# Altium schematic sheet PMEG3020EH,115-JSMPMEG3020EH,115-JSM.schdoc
size 127 x 101 mm
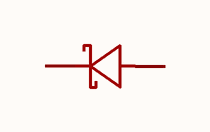
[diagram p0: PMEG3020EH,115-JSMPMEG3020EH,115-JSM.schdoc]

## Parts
D?  pmeg3020eh,115-jsm  [SOD-123FL_L2.7-W1.8-LS3.7-RD]  (value not drawn)

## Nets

Not connected (* = marked no-connect by the designer): D? 1(K) 2(A)

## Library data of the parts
D? = pmeg3020eh,115-jsm: 二极管配置:1个独立式;正向压降(Vf):550mV@3A;直流反向耐压(Vr):20V;整流电流:3A;; Manufacturer: JSMSEMI(杰盛微); AddInBom: yes; ModelId: 86f9151e155e4fe2af0c4f2e0a80302e; ModelName: SOD-123FL_L2.8-W1.8-H1.1-LS3.6; ModelTransform: 141.732,70.866,0,180,0,0,0,0,0; Diode Configuration: 1个独立式; Voltage - DC Reverse(Vr): 20V; Current - Rectified: 3A; Reverse Leakage Current (Ir): 500uA@20V; Operating Junction Temperature Range: -55℃~+150℃; Non-Repetitive Peak Forward Surge Current: 100A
